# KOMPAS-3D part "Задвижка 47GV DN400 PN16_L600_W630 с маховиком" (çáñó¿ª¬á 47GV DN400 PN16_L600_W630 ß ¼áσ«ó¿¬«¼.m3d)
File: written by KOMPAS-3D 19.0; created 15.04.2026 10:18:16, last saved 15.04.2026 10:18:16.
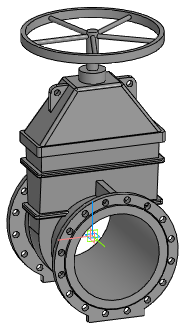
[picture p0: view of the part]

Document properties: Автор: Евгений; Полное имя файла: Z:\3.Личные\kachalov\3d для проектировщиков\2.1 Тип 47GV, 47GV.Z\Задвижка 47GV_DN40-DN600\stp_Задвижка 47GV\Задвижка 47GV DN400 PN16_L600_W630 с маховиком.m3d

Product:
- Part/product: Задвижка 47GV DN400 PN16_L600_W630 с маховиком

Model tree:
1. Операция без истории:1  (labels: Задвижка 47GV DN400 PN16_L600_W630 с маховиком)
